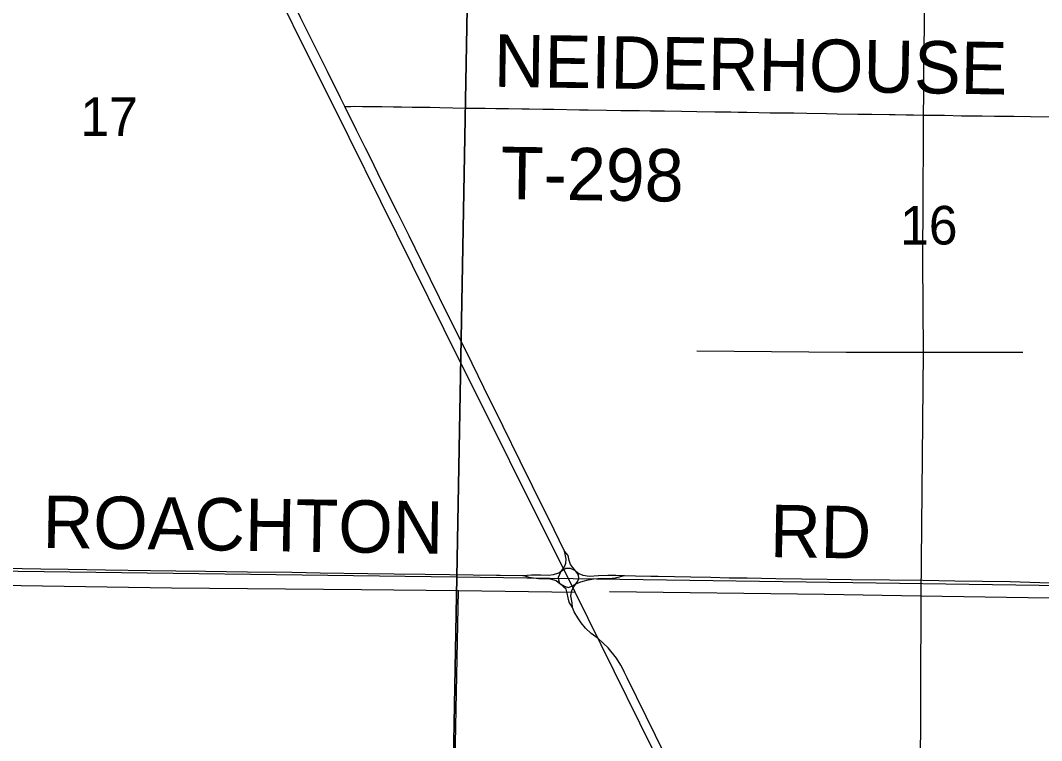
# Model space of a CAD drawing. Extents: x 0 to 34, y 0 to 22.
# Drawn here: x 3.943 to 5.051, y 14.756 to 15.537 of the extents above; entities that cross this region are included whole.
import ezdxf

# ---------------------------------------------------------------- set-up
doc = ezdxf.new("R2010")
doc.units = 0
for name, color, linetype in [('GM_X_Corporation', 7, 'Continuous'), ('GM_X_County_Road', 7, 'Continuous'), ('GM_X_County_Road_Text', 7, 'Continuous'), ('GM_X_Minor_River', 7, 'Continuous'), ('GM_X_Section_Text', 7, 'Continuous'), ('GM_X_State_Route', 7, 'Continuous'), ('GM_X_Township_Road', 7, 'Continuous'), ('GM_X_Township_Road_Text', 7, 'Continuous')]:
    doc.layers.add(name, color=color, linetype=linetype)

msp = doc.modelspace()

# ---------------------------------------------------------------- linework, layer by layer
at = {"layer": 'GM_X_Corporation'}
for points in [[(3.4216, 15.9505), (4.4354, 15.9477), (4.4167, 14.9334), (3.4087, 14.9463)], [(4.4354, 15.9477), (5.4509, 15.9313), (5.428, 14.9189), (4.4167, 14.9334)], [(3.396, 14.1), (4.4016, 14.1), (4.4167, 14.9334), (3.4087, 14.9463)], [(4.4016, 14.1), (5.4122, 14.1), (5.428, 14.9189), (4.4167, 14.9334)]]:
    msp.add_lwpolyline(points, close=True, dxfattribs=at)
at = {"layer": 'GM_X_County_Road'}
msp.add_line((4.4885, 14.9352), (4.4895, 14.9349), dxfattribs=at)
for points in [[(3.9086, 14.9432), (3.9248, 14.943), (3.9652, 14.9424), (3.995, 14.942), (4.0354, 14.9413), (4.0845, 14.9405), (4.1119, 14.9402), (4.1442, 14.9397), (4.1896, 14.9391), (4.2381, 14.9386), (4.2686, 14.9381), (4.3202, 14.9374), (4.3487, 14.937), (4.3823, 14.9366), (4.4091, 14.9361), (4.4597, 14.9356)], [(4.4885, 14.9352), (4.498, 14.9359), (4.5078, 14.9358), (4.5163, 14.9354), (4.5217, 14.9361), (4.5275, 14.938), (4.5304, 14.9402), (4.5352, 14.9429), (4.5399, 14.943), (4.5432, 14.9417), (4.5456, 14.94), (4.5491, 14.9372), (4.5537, 14.9353), (4.5608, 14.9345), (4.5704, 14.935), (4.5805, 14.9353), (4.5893, 14.9354), (4.5988, 14.9349)], [(4.4597, 14.9356), (4.4638, 14.9356), (4.4885, 14.9352)], [(4.4895, 14.9349), (4.4951, 14.9334), (4.5053, 14.9319), (4.5133, 14.9318), (4.5182, 14.9314), (4.5245, 14.9295), (4.5287, 14.9264), (4.5344, 14.923), (4.5381, 14.9222), (4.5424, 14.9237), (4.5458, 14.9259)], [(4.5458, 14.9259), (4.5502, 14.9278), (4.5539, 14.9291), (4.5594, 14.9305), (4.5654, 14.9316), (4.5738, 14.9322), (4.5814, 14.9319), (4.5889, 14.9326), (4.5988, 14.9349)], [(4.5988, 14.9349), (4.6106, 14.9348), (4.6273, 14.9344), (4.6352, 14.9342)], [(4.6352, 14.9342), (4.6708, 14.9336), (4.6925, 14.9331), (4.7124, 14.9327), (4.7317, 14.9325), (4.7628, 14.932), (4.8187, 14.9312), (4.8448, 14.9309), (4.8865, 14.9303), (4.9226, 14.9299), (4.9574, 14.9294), (5.0171, 14.9284), (5.0494, 14.9276), (5.1414, 14.9258), (5.1886, 14.9251), (5.2607, 14.9239), (5.3409, 14.922), (5.3614, 14.9216), (5.4198, 14.9204), (5.4337, 14.9202)]]:
    msp.add_lwpolyline(points, dxfattribs=at)
at = {"layer": 'GM_X_Minor_River'}
for points in [[(4.9859, 17.7695), (4.9787, 17.5661), (4.97, 17.2993), (4.9652, 17.1654), (4.9566, 16.932), (4.9509, 16.7564), (4.9406, 16.3952), (4.9347, 16.1774), (4.9302, 15.9217), (4.9265, 15.7213), (4.9234, 15.4796), (4.9222, 15.2762), (4.9228, 15.1771), (4.9205, 14.913), (4.9191, 14.6003), (4.9178, 14.4421)], [(4.9429, 14.112), (4.8226, 14.3541), (4.6577, 14.6894), (4.5451, 14.917), (4.403, 15.2019), (4.2999, 15.41), (4.178, 15.6548), (4.0606, 15.8912), (3.9943, 16.0226), (4.0516, 16.097), (4.1146, 16.177), (4.1979, 16.2845), (4.2667, 16.3732), (4.3266, 16.4473), (4.3362, 16.4604), (4.3416, 16.4642), (4.3499, 16.4656), (4.3607, 16.4654)], [(4.6773, 15.1787), (4.8393, 15.1774), (4.9228, 15.1771), (5.0312, 15.1773)], [(3.4735, 14.9308), (3.5332, 14.9296), (3.6692, 14.9272), (3.8969, 14.9251), (4.1073, 14.9217), (4.3132, 14.9199), (4.4185, 14.9189), (4.5451, 14.917)], [(4.4003, 14.1), (4.4003, 14.1013), (4.4063, 14.3236), (4.4102, 14.5429), (4.4141, 14.6977), (4.4185, 14.9189)], [(4.5825, 14.9176), (4.8159, 14.9147), (4.9205, 14.913), (5.0599, 14.9109), (5.2329, 14.9087), (5.3008, 14.9079)]]:
    msp.add_lwpolyline(points, dxfattribs=at)
at = {"layer": 'GM_X_State_Route'}
msp.add_line((4.5338, 14.9616), (4.5165, 14.9965), dxfattribs=at)
for points in [[(4.2952, 15.4437), (4.2905, 15.4532), (4.2765, 15.4816), (4.2476, 15.5395), (4.2261, 15.583), (4.2119, 15.6113), (4.1887, 15.6588), (4.175, 15.686)], [(4.5165, 14.9965), (4.5119, 15.0057), (4.499, 15.0319), (4.4856, 15.0592), (4.4671, 15.0966), (4.4461, 15.1389), (4.4272, 15.1775), (4.4079, 15.2164), (4.3784, 15.2761), (4.3649, 15.3034), (4.3527, 15.3279), (4.3355, 15.3624), (4.3226, 15.3886), (4.3176, 15.3986), (4.308, 15.4181), (4.2952, 15.4437)], [(4.5321, 14.9232), (4.5287, 14.9264), (4.5276, 14.9299), (4.5272, 14.9332), (4.5284, 14.9364), (4.5304, 14.9402), (4.5338, 14.9445), (4.535, 14.9486), (4.5354, 14.9527), (4.5348, 14.9564), (4.5338, 14.9616)], [(4.5456, 14.94), (4.5426, 14.9437), (4.5401, 14.9469), (4.5386, 14.9514), (4.5377, 14.9566), (4.5338, 14.9616)], [(4.5436, 14.9227), (4.5458, 14.9259), (4.5482, 14.9291), (4.5492, 14.9323), (4.5488, 14.9354), (4.5477, 14.9374), (4.5456, 14.94)], [(4.5425, 14.9002), (4.5388, 14.9062), (4.5375, 14.911), (4.5365, 14.9159), (4.5353, 14.9201), (4.5328, 14.9225), (4.5321, 14.9232)], [(4.5425, 14.9002), (4.5421, 14.9054), (4.5406, 14.9129), (4.5417, 14.9187), (4.5436, 14.9227)], [(4.5983, 14.8308), (4.5949, 14.8378), (4.59, 14.8456), (4.581, 14.8565), (4.5702, 14.8666), (4.5625, 14.8722), (4.5564, 14.8779), (4.5518, 14.8836), (4.548, 14.8892), (4.5443, 14.8957), (4.5425, 14.9002)], [(4.6573, 14.7107), (4.6324, 14.7615), (4.6222, 14.7821), (4.6017, 14.824), (4.5988, 14.8299), (4.5983, 14.8308)]]:
    msp.add_lwpolyline(points, dxfattribs=at)
at = {"layer": 'GM_X_Township_Road'}
msp.add_lwpolyline([(4.2952, 15.4437), (4.3019, 15.4438), (4.3056, 15.4439), (4.3143, 15.4438), (4.3355, 15.4435), (4.3479, 15.4434), (4.3566, 15.4433), (4.3684, 15.4431), (4.3877, 15.4428), (4.3983, 15.4426), (4.4126, 15.4423), (4.4262, 15.442), (4.4343, 15.4419), (4.4474, 15.4418), (4.4592, 15.4415), (4.4729, 15.4414), (4.4872, 15.4412), (4.4952, 15.4411), (4.5102, 15.4409), (4.522, 15.4406), (4.55, 15.4401), (4.5593, 15.4401), (4.5792, 15.4398), (4.5947, 15.4394), (4.6152, 15.4393), (4.6271, 15.4391), (4.642, 15.439), (4.6606, 15.4386), (4.6774, 15.4384), (4.6967, 15.438), (4.7054, 15.438), (4.7141, 15.4379), (4.7222, 15.4376), (4.7315, 15.4374), (4.7446, 15.4372), (4.757, 15.4369), (4.7725, 15.4369), (4.7825, 15.4367), (4.7968, 15.4365), (4.8179, 15.4361), (4.8297, 15.4358), (4.8521, 15.4355), (4.867, 15.4354), (4.8863, 15.435), (4.8925, 15.4349), (4.9043, 15.4347), (4.9124, 15.4345), (4.9224, 15.4344), (4.946, 15.4341), (4.9646, 15.4337), (4.987, 15.4335), (5.0001, 15.4332), (5.0212, 15.433), (5.0393, 15.4327), (5.0598, 15.4324)], dxfattribs=at)

# ---------------------------------------------------------------- texts
at = {"layer": 'GM_X_County_Road_Text'}
for s, rotation, p in [('ROACHTON', 359.1386, (3.967, 14.9651)), ('RD', 359.0179, (4.7563, 14.9551))]:
    msp.add_text(s, height=0.05682, rotation=rotation, dxfattribs=at).set_placement(p)
at = {"layer": 'GM_X_Section_Text'}
for s, p in [('17', (4.0083, 15.4117)), ('16', (4.8979, 15.294))]:
    msp.add_text(s, height=0.04186, rotation=0, dxfattribs=at).set_placement(p)
at = {"layer": 'GM_X_Township_Road_Text'}
for s, height, rotation, p in [('NEIDERHOUSE', 0.056818, 359.1234, (4.4567, 15.4651)), ('T-298', 0.05682, 359.1587, (4.4641, 15.3433))]:
    msp.add_text(s, height=height, rotation=rotation, dxfattribs=at).set_placement(p)

doc.saveas('drawing.dxf')
